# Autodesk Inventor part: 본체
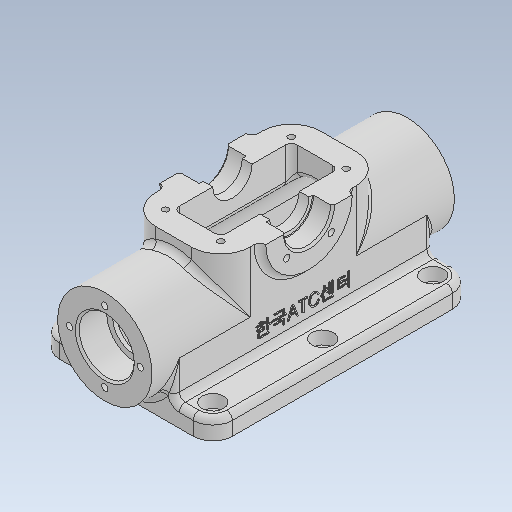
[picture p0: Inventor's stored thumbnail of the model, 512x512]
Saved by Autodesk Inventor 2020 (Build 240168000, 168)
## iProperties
Created: 2024-07
Part Number: 본체
Material: 일반
Document SubType Name: Modeling
Designer: oem
Density: 1 g/cm^3
Appearance: 기본값
Author: jhkim
Sending System: Autodesk Inventor 2025
Preprocessor: ST-DEVELOPER v20
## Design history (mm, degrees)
feature "솔리드1"
node "솔리드2"
